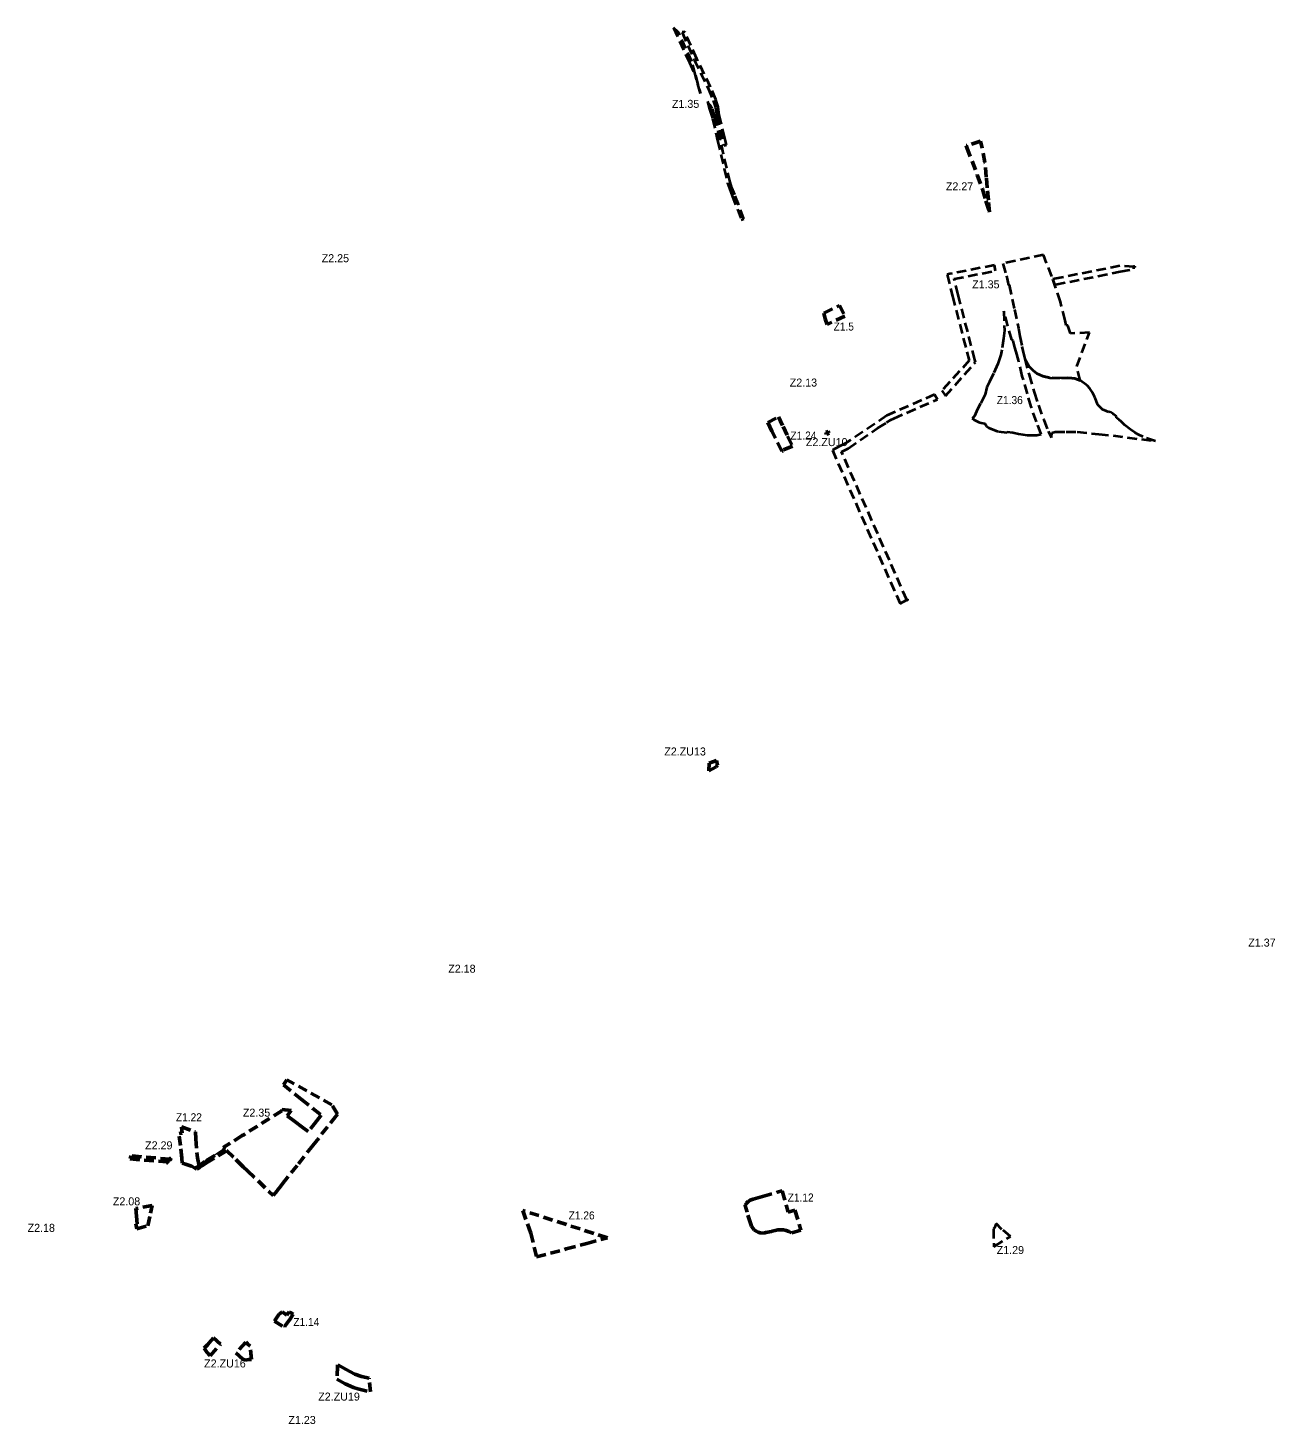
# Model space of a CAD drawing. Extents: x -650368 to -643203, y -1074215 to -1066658.
# Drawn here: x -650368 to -647095, y -1070321 to -1066658 of the extents above; entities that cross this region are included whole.
import ezdxf
from ezdxf.enums import TextEntityAlignment as Align

# ---------------------------------------------------------------- set-up
doc = ezdxf.new("R2010")
doc.units = 0
doc.header["$LTSCALE"] = 8.4
doc.header["$PDMODE"] = 32
doc.header["$PDSIZE"] = 4.2
doc.linetypes.add('MEDIUM_DASHED', pattern=[4.5, 3, -1.5])
for name, color, linetype, lineweight in [('1', 7, 'Continuous', 13), ('57', 7, 'MEDIUM_DASHED', 40), ('58', 7, 'MEDIUM_DASHED', 53)]:
    doc.layers.add(name, color=color, linetype=linetype, lineweight=lineweight)
for name, color, linetype in [('60', 7, 'Continuous'), ('61', 7, 'Continuous'), ('62', 7, 'Continuous')]:
    doc.layers.add(name, color=color, linetype=linetype)

msp = doc.modelspace()

# ---------------------------------------------------------------- linework, layer by layer
at = {"layer": '1'}
msp.add_line((-649849.496, -1069598.673), (-649903.756, -1069631.653), dxfattribs=at)
at = {"layer": '57'}
for p, q in [((-648495.63, -1067161.363), (-648489.1, -1067158.84)), ((-647408.2, -1067742.37), (-647440.81, -1067731.38))]:
    msp.add_line(p, q, dxfattribs=at)
for points in [[(-648602.97, -1066830.11), (-648616.86, -1066779.79), (-648625.44, -1066746.45), (-648659.95, -1066670.89), (-648662.46, -1066668.53), (-648673.407, -1066658.275), (-648631.791, -1066749.394)], [(-648576.145, -1066813.802), (-648612.763, -1066739.165), (-648643.925, -1066668.483), (-648651.042, -1066669.551), (-648651.1, -1066669.56)], [(-648651.1, -1066669.56), (-648619.11, -1066742.12), (-648582.52, -1066816.7)], [(-648631.791, -1066749.394), (-648616.104, -1066782.727), (-648602.97, -1066830.11)], [(-648582.52, -1066816.7), (-648569.13, -1066848.61), (-648566.63, -1066856.72), (-648563.48, -1066866.96), (-648560.2, -1066888.58), (-648541.521, -1066966.657), (-648534.701, -1066965.077), (-648538.812, -1066947.891)], [(-648538.812, -1066947.891), (-648553.323, -1066887.238), (-648556.637, -1066865.397), (-648559.94, -1066854.66), (-648562.542, -1066846.219), (-648576.145, -1066813.802)], [(-648571.96, -1066869.37), (-648577.99, -1066860.17), (-648583.94, -1066851.11), (-648578.702, -1066871.259)], [(-648578.702, -1066871.259), (-648571.167, -1066896.326), (-648557.816, -1066953.444)], [(-648489.1, -1067158.84), (-648512.95, -1067095.97), (-648520.4, -1067077.42), (-648524.93, -1067063.35), (-648533.66, -1067026), (-648551, -1066951.85), (-648564.4, -1066894.52), (-648571.96, -1066869.37)], [(-648557.816, -1066953.444), (-648540.476, -1067027.594), (-648531.681, -1067065.222)], [(-648531.681, -1067065.222), (-648526.988, -1067079.8), (-648519.471, -1067098.516), (-648495.644, -1067161.326)], [(-647638.68, -1067439.06), (-647642.686, -1067438.46), (-647645.78, -1067425.81), (-647658.13, -1067376.99), (-647680.64, -1067310.37), (-647702.42, -1067253.98), (-647809.02, -1067276.271)], [(-647809.02, -1067276.271), (-647799.76, -1067308.3), (-647794.54, -1067333.14)], [(-647948.488, -1067303.671), (-647955.805, -1067305.106), (-647941.289, -1067362.104)], [(-647882.66, -1067529.231), (-647926.759, -1067358.379), (-647937.355, -1067316.774), (-647828.376, -1067295.406), (-647828.104, -1067295.352), (-647831.28, -1067280.69), (-647948.488, -1067303.671)], [(-647465.203, -1067285.115), (-647501.968, -1067282.642), (-647673.685, -1067316.666), (-647678.21, -1067317.562), (-647673.367, -1067331.895), (-647670.77, -1067331.38), (-647501.099, -1067297.762)], [(-647501.099, -1067297.762), (-647465.699, -1067290.747), (-647465.203, -1067285.115)], [(-647794.54, -1067333.14), (-647792.52, -1067332.74), (-647778.78, -1067397.1), (-647768.5, -1067446.04), (-647764.89, -1067466.64), (-647759.16, -1067494.01)], [(-647941.289, -1067362.104), (-647897.637, -1067531.223), (-647969.29, -1067609.79), (-647959.832, -1067623.65)], [(-647773.96, -1067508.48), (-647777.55, -1067496.95), (-647781.85, -1067479.19), (-647785.64, -1067477.02), (-647806.8, -1067401.51), (-647804.88, -1067452.07), (-647807.17, -1067473.06), (-647811.8, -1067502.42), (-647814.89, -1067515.91), (-647822.82, -1067539.89), (-647833.51, -1067565.03), (-647844.04, -1067587.17)], [(-647751.41, -1067526.58), (-647740.124, -1067546.265), (-647729.802, -1067557.462), (-647719.661, -1067564.884), (-647704.458, -1067572.034), (-647685.968, -1067576.68), (-647654.743, -1067576.996), (-647640.087, -1067576.306), (-647628.441, -1067576.759), (-647620.586, -1067578.478), (-647606.559, -1067583.309), (-647614.75, -1067546.53), (-647582.2, -1067457.65), (-647631.59, -1067459.72), (-647638.68, -1067439.06)], [(-647759.16, -1067494.01), (-647756.55, -1067505.32), (-647751.41, -1067526.58)], [(-647959.832, -1067623.65), (-647881.085, -1067535.333), (-647882.66, -1067529.231)], [(-647708.71, -1067723.99), (-647721.05, -1067691.73), (-647734.63, -1067652.57), (-647744.61, -1067617.96), (-647758.25, -1067571.79), (-647768.5, -1067529.75), (-647773.96, -1067508.48)], [(-647547.663, -1067659.519), (-647560.187, -1067647.458), (-647567.744, -1067627.24), (-647573.605, -1067614.951), (-647580.539, -1067604.432), (-647586.864, -1067597.411), (-647591.227, -1067593.613), (-647604.415, -1067584.047), (-647620.586, -1067578.478), (-647628.441, -1067576.759), (-647640.087, -1067576.306), (-647654.743, -1067576.996), (-647685.968, -1067576.68), (-647704.458, -1067572.034), (-647719.661, -1067564.884), (-647729.802, -1067557.462), (-647740.124, -1067546.265), (-647751.41, -1067526.58)], [(-647751.41, -1067526.58), (-647740.49, -1067568.67), (-647727.37, -1067614.33), (-647715.92, -1067648.12), (-647702.04, -1067686.86), (-647690.09, -1067716.05), (-647681.91, -1067732.74)], [(-647844.04, -1067587.17), (-647850.96, -1067600.4), (-647855.65, -1067620.33), (-647867.53, -1067643.84)], [(-647988.235, -1067619.912), (-648114.145, -1067675.531), (-648222.872, -1067748.412), (-648238.748, -1067756.759), (-648256.499, -1067766.091), (-648079.002, -1068168.139), (-648061.329, -1068158.649)], [(-648215.115, -1067761.28), (-648137.869, -1067708.325), (-648114.323, -1067693.403), (-648103.383, -1067686.47), (-648103.298, -1067686.416), (-648095.475, -1067682.994), (-647983.403, -1067633.963), (-647983.06, -1067633.813), (-647980.561, -1067632.719), (-647982.95, -1067628.73), (-647988.235, -1067619.912)], [(-647867.53, -1067643.84), (-647876.15, -1067658.82), (-647883.78, -1067676.59), (-647886.95, -1067680.13), (-647889.94, -1067681.81)], [(-647889.94, -1067681.81), (-647884.25, -1067686.21), (-647882.82, -1067687.32), (-647871.87, -1067692.85), (-647869.32, -1067693.61), (-647865.76, -1067694.68), (-647856.9, -1067695.97)], [(-647499.095, -1067691.163), (-647503.97, -1067686.73), (-647510.6, -1067680.86), (-647511.24, -1067677.53), (-647517.74, -1067672.85), (-647520.13, -1067671.13), (-647527.76, -1067665.65), (-647530.82, -1067666.65), (-647536.83, -1067663.64), (-647547.663, -1067659.519)], [(-647856.9, -1067695.97), (-647852.3, -1067703.36), (-647845.74, -1067707.59), (-647821.02, -1067717.33), (-647798.5, -1067719.67), (-647798.17, -1067717.58), (-647783.13, -1067719.68), (-647768.53, -1067722.82), (-647745.41, -1067726.6), (-647732.71, -1067727.02), (-647720.45, -1067726.49), (-647708.71, -1067723.99)], [(-647681.91, -1067732.74), (-647680.804, -1067720.745), (-647672, -1067718), (-647643, -1067718), (-647614, -1067718), (-647557, -1067724), (-647520.145, -1067727.879), (-647408.2, -1067742.37)], [(-647440.81, -1067731.38), (-647453.87, -1067724.97), (-647462.45, -1067719.84), (-647474.13, -1067711.81), (-647489.3, -1067700.07), (-647499.095, -1067691.163)], [(-648061.329, -1068158.649), (-648232.676, -1067770.513), (-648215.115, -1067761.28)]]:
    msp.add_lwpolyline(points, dxfattribs=at)
at = {"layer": '57', "lineweight": 53}
for points in [[(-648279.24, -1067406.38), (-648237.881, -1067386.158), (-648237.873, -1067386.174), (-648237.865, -1067386.17), (-648224.19, -1067414.14), (-648270.02, -1067436.37), (-648275.41, -1067421.3)], [(-648397.98, -1067678.79), (-648385.86, -1067704.19), (-648373.99, -1067728.95), (-648361.08, -1067755.88), (-648387.04, -1067765.67), (-648386.12, -1067767.45), (-648389.29, -1067768.64), (-648415.164, -1067716.136), (-648426.366, -1067693.402)], [(-649967.81, -1069590.74), (-649971.38, -1069558.79), (-649963.43, -1069557.91), (-649965.26, -1069541.51), (-649928.48, -1069554.57), (-649927.304, -1069572.44), (-649924.62, -1069608.53), (-649923.17, -1069623.14), (-649918.354, -1069643.452), (-649917.38, -1069647.56), (-649924.8, -1069652.19), (-649928.67, -1069649.89), (-649938.2, -1069644.23), (-649954.38, -1069639.1), (-649962.71, -1069636.46), (-649964.11, -1069623.91)], [(-648339.05, -1069812.45), (-648363.68, -1069819.31), (-648371.21, -1069815.56), (-648378.1, -1069813.29), (-648385.21, -1069811.91), (-648392.45, -1069811.44), (-648399.68, -1069811.88), (-648406.84, -1069813.23), (-648414.657, -1069815.246), (-648415.99, -1069815.59), (-648430.881, -1069818.663), (-648433.97, -1069819.3), (-648439.89, -1069819.97), (-648445.8, -1069819.51), (-648451.53, -1069817.98), (-648456.88, -1069815.39), (-648461.64, -1069811.86), (-648465.67, -1069807.49), (-648468.82, -1069802.44), (-648470.97, -1069796.9), (-648480.267, -1069765.316), (-648485.44, -1069747.39), (-648485.14, -1069746.55), (-648483.274, -1069743.777), (-648481.79, -1069741.57), (-648477.39, -1069737.44), (-648476.022, -1069736.525), (-648472.4, -1069734.1), (-648464.45, -1069730.89), (-648439.8, -1069724.19), (-648401.288, -1069713.154), (-648388.631, -1069709.738), (-648372.639, -1069765.241), (-648355.015, -1069760.287)], [(-649069.4, -1069760.67), (-649048, -1069820), (-649032.928, -1069882.782), (-648955.211, -1069861.806), (-648901.185, -1069847.225), (-648846.924, -1069832.58)], [(-649676.46, -1070039.89), (-649671.82, -1070033.15), (-649678.92, -1070028.51), (-649682.07, -1070026.45), (-649686.55, -1070033.29), (-649688.24, -1070035.47), (-649692, -1070033.14), (-649691.64, -1070032.56), (-649700.69, -1070026.36), (-649709.67, -1070034.09), (-649718.51, -1070046.94), (-649721.11, -1070051.18), (-649694.06, -1070067.08), (-649693.23, -1070065.13), (-649691.7, -1070062.02), (-649685.84, -1070053.65), (-649679.2, -1070044.17)]]:
    msp.add_lwpolyline(points, close=True, dxfattribs=at)
at = {"layer": '57'}
msp.add_lwpolyline([(-647833.172, -1069855.944), (-647833.172, -1069855.944), (-647831.62, -1069854.99), (-647789.55, -1069829.12), (-647811.83, -1069810.39), (-647827.16, -1069795.32), (-647831.32, -1069806.56), (-647833.91, -1069808.91), (-647833.2, -1069854.15)], close=True, dxfattribs=at)
for p in [(-647465.203, -1067285.115), (-648061.329, -1068158.649)]:
    msp.add_point(p, dxfattribs=at)
at = {"layer": '58'}
for points in [[(-647903.5, -1066972.05), (-647876.57, -1067043.5), (-647863.04, -1067081.36), (-647853.65, -1067111.91), (-647844.3, -1067141.25), (-647847.09, -1067110.58), (-647850.07, -1067077.71), (-647852.63, -1067049.52), (-647856.11, -1067011.21), (-647866.14, -1066961.98), (-647867.46, -1066955.52), (-647905.28, -1066967.07)], [(-648267.25, -1067716.9), (-648273.97, -1067719.29), (-648272.02, -1067724.45), (-648269.15, -1067723.37), (-648264.95, -1067721.79)], [(-648579.97, -1068587.39), (-648580.66, -1068607.64), (-648561.49, -1068596.84), (-648558.08, -1068592.36), (-648560.79, -1068580.12)], [(-650002.39, -1069633.65), (-649994.913, -1069626.246), (-650096.627, -1069617.746), (-650099.55, -1069625.53), (-650062.45, -1069628.63)], [(-649897.03, -1070113.07), (-649905.51, -1070122.35), (-649898.55, -1070132.9), (-649889.87, -1070141.83), (-649862.22, -1070111.54), (-649880.42, -1070094.87), (-649886.83, -1070101.89)], [(-649784.87, -1070116.76), (-649791.58, -1070110.83), (-649796.4, -1070106.56), (-649821.97, -1070134.58), (-649804.29, -1070150.68), (-649797.33, -1070153.41), (-649787.92, -1070152.23), (-649781.432, -1070151.628)], [(-649557.21, -1070203.53), (-649535, -1070216), (-649513, -1070225), (-649502.36, -1070228.94), (-649469.02, -1070236.92), (-649472.43, -1070202.9), (-649472.6, -1070201.15), (-649492.67, -1070196.34), (-649509.72, -1070190.24), (-649523.21, -1070183.06), (-649532.57, -1070178.08), (-649555.44, -1070165.91), (-649555.15, -1070169.51)]]:
    msp.add_lwpolyline(points, close=True, dxfattribs=at)
for points in [[(-649688.625, -1069418.156), (-649697.525, -1069431.522), (-649650.425, -1069468.85), (-649619.983, -1069493.184), (-649598.004, -1069510.814), (-649610.429, -1069526.497), (-649632.179, -1069553.95), (-649649.31, -1069541.16), (-649667.74, -1069527.4), (-649687.77, -1069512.44), (-649677.02, -1069498.32), (-649701.7, -1069495.89), (-649701.57, -1069499.21), (-649801.49, -1069561.98), (-649805.22, -1069564.32), (-649855.34, -1069595.8), (-649850.24, -1069600.295), (-649877.129, -1069617.006), (-649903.292, -1069632.541), (-649918.35, -1069643.45), (-649928.67, -1069649.89), (-649924.8, -1069652.19), (-649920.45, -1069649.53), (-649917.38, -1069647.56), (-649907.07, -1069640.92), (-649900.64, -1069636.78), (-649846.38, -1069603.8), (-649822.26, -1069627.2), (-649818.71, -1069630.64), (-649802.9, -1069645.96), (-649791.3, -1069657.21)], [(-649561.17, -1069515.83), (-649558.71, -1069512.62), (-649555.16, -1069508.07), (-649570.03, -1069483.83), (-649688.625, -1069418.156)], [(-649620.45, -1069590.75), (-649574.1, -1069531.97), (-649571.94, -1069529.24), (-649561.17, -1069515.83)], [(-649724.51, -1069721.57), (-649714.03, -1069709.09), (-649712.64, -1069707.43), (-649705.28, -1069698.11), (-649700.42, -1069691.8), (-649658.13, -1069638.84), (-649620.45, -1069590.75)], [(-649791.3, -1069657.21), (-649763.31, -1069683.5), (-649763.31, -1069683.5), (-649724.51, -1069721.57)], [(-650084.48, -1069755.86), (-650082.63, -1069775.78), (-650080.78, -1069795.7), (-650084.63, -1069796.06), (-650081.66, -1069808.87), (-650053.2, -1069801.11)], [(-650053.2, -1069801.11), (-650046.28, -1069767.47), (-650041.591, -1069747.598), (-650084.48, -1069755.86)]]:
    msp.add_lwpolyline(points, dxfattribs=at)
for p in [(-650002.39, -1069633.65), (-649994.913, -1069626.246)]:
    msp.add_point(p, dxfattribs=at)

# ---------------------------------------------------------------- texts
at = {"layer": '60'}
for s, p in [('Z1.35', (-648641.847, -1066868.029)), ('Z1.35', (-647853.88, -1067341.475)), ('Z1.37', (-647129.255, -1069068.508)), ('Z1.29', (-647789.527, -1069875.149)), ('Z1.23', (-649648.392, -1070320.945))]:
    msp.add_text(s, height=21, dxfattribs=at).set_placement(p, align=Align.CENTER)
at = {"layer": '60', "width": 0.95}
for s, p in [('Z1.5', (-648226.743, -1067452.194)), ('Z1.36', (-647790.96, -1067645.188)), ('Z1.24', (-648332.556, -1067738.122)), ('Z1.22', (-649945.368, -1069526.711)), ('Z1.12', (-648339.89, -1069737.306)), ('Z1.26', (-648914.702, -1069784.313)), ('Z1.14', (-649637.253, -1070063.973))]:
    msp.add_text(s, height=21, dxfattribs=at).set_placement(p, align=Align.CENTER)
at = {"layer": '61'}
for s, p in [('Z2.27', (-647922.882, -1067084.411)), ('Z2.ZU10', (-648271.539, -1067755.404)), ('Z2.ZU13', (-648643.248, -1068567.089)), ('Z2.35', (-649767.849, -1069514.654)), ('Z2.29', (-650024.478, -1069600.414)), ('Z2.08', (-650109.101, -1069747.403)), ('Z2.ZU16', (-649850.907, -1070172.691)), ('Z2.ZU19', (-649551.432, -1070259.616))]:
    msp.add_text(s, height=21, dxfattribs=at).set_placement(p, align=Align.CENTER)
at = {"layer": '62'}
for s, p in [('Z2.25', (-649561.009, -1067272.925)), ('Z2.13', (-648332.638, -1067599.204)), ('Z2.18', (-649228.931, -1069136.994)), ('Z2.18', (-650332.906, -1069816.873))]:
    msp.add_text(s, height=21, dxfattribs=at).set_placement(p, align=Align.CENTER)

doc.saveas('drawing.dxf')
